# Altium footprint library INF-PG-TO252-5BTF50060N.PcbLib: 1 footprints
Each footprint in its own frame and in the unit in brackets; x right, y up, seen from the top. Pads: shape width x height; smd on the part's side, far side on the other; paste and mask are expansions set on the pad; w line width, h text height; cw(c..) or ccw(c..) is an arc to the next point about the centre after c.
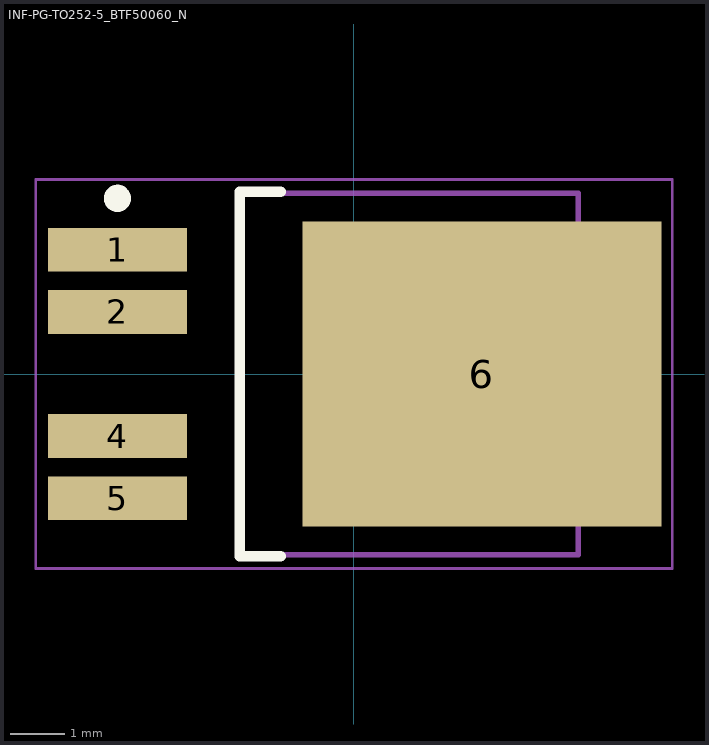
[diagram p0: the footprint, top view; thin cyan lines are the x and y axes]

## INF-PG-TO252-5_BTF50060_N [mm] "DPAK, 5-Leads, Body 6.5x6.12mm, Pitch 1.14mm, IPC Medium Density"
height 2.35
pads (5):
  rect 2.55x0.8 smd: 1(-4.35,2.28) 2(-4.35,1.14) 4(-4.35,-1.14) 5(-4.35,-2.28)
  rect 6.6x5.6 smd: 6(2.35,0)
Top Overlay:
  circle w0.25: c-4.35,3.23 r0.125
  lines w0.2: -1.35,-3.35 -2.1,-3.35 -2.1,3.35 -1.35,3.35
Mechanical 13:
  lines w0.1: -2.1,-3.325 -2.1,3.325 4.12,3.325 4.12,-3.325 -2.1,-3.325
Mechanical 15:
  lines w0.05: -5.85,-3.575 -5.85,3.575 5.85,3.575 5.85,-3.575 -5.85,-3.575
  lines w0.1: -0.5,0 0.5,0 ; 0,-0.5 0,0.5
3D body: height 2.35, standoff 0, extent -2.1,-3.325 4.12,3.325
